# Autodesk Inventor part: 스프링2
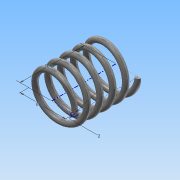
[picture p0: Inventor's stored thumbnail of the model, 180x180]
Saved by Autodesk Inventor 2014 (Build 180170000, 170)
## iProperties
Created: 2016-01
Part Number: 스프링2
Material: 강철, 탄소
Document SubType Name: Modeling
Designer: Administrator
Mass: 6.66264 g
Surface Area: 16.7518 cm^2
Volume: 0.824584 cm^3
Density: 8.08 g/cm^3
Appearance: 반연마
Author: Administrator
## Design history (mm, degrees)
sketch "스케치1"
  geometry: L1 (0, 0)-(8.5, 0); L2 (8.5, 0)-(8.5, 20.5); L3 (8.5, 20.5)-(0, 20.5); L4 (0, 20.5)-(0, 0); C1 r 1 at (8.5, 0)
  constraints: 8 end point, 2 parallel, 1 centre point, 1 coincident, 1 horizontal, 1 perpendicular
  dimensions: "d0" = 2 diameter of C1; "d1" = 17 diameter of L2 L4; "d2" = 20.5 distance of L3.end L1.start (derived)
feature "코일1" sketch "스케치1" pitch "d3" = 10; turns "d5" = 5; dims "d4" = 20.5 (= d2), "d6" = 0, angle "d7" = 90 deg, angle "d8" = 90 deg, "d9" = 0, "d10" = 0
node "작업 평면1"
sketch "스케치2"
  geometry: L1 (-9.5, 0)-(-7.5, 0) reference; 1 further point
  constraints: 1 horizontal alignment
extrude "돌출1" cut sketch "스케치2" distance "d12" = 10; taper "d13" = 0 deg
node "작업 평면2"
sketch "스케치3"
  geometry: L1 (-7.5, 0)-(-9.5, 0) reference; 1 further point
  constraints: 1 horizontal alignment
extrude "돌출2" cut sketch "스케치3" distance "d15" = 10; taper "d16" = 0 deg
node "솔리드1"
node "절단 모서리 투영1"
node "절단 모서리 투영2"
other parameters: "d11" = 20.5 (= d2), "d14" = 0
